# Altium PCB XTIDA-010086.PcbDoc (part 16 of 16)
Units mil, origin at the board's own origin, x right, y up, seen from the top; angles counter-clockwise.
Board outline 14763.78 x 8267.72 mil, 6 copper layers (Top Layer, GND Layer, Signal Layer 1, Signal Layer 2, Power Layer, Bottom Layer), stack 62 mil thick; 1933 components, 1002 nets, 4886 pads, 6482 vias.
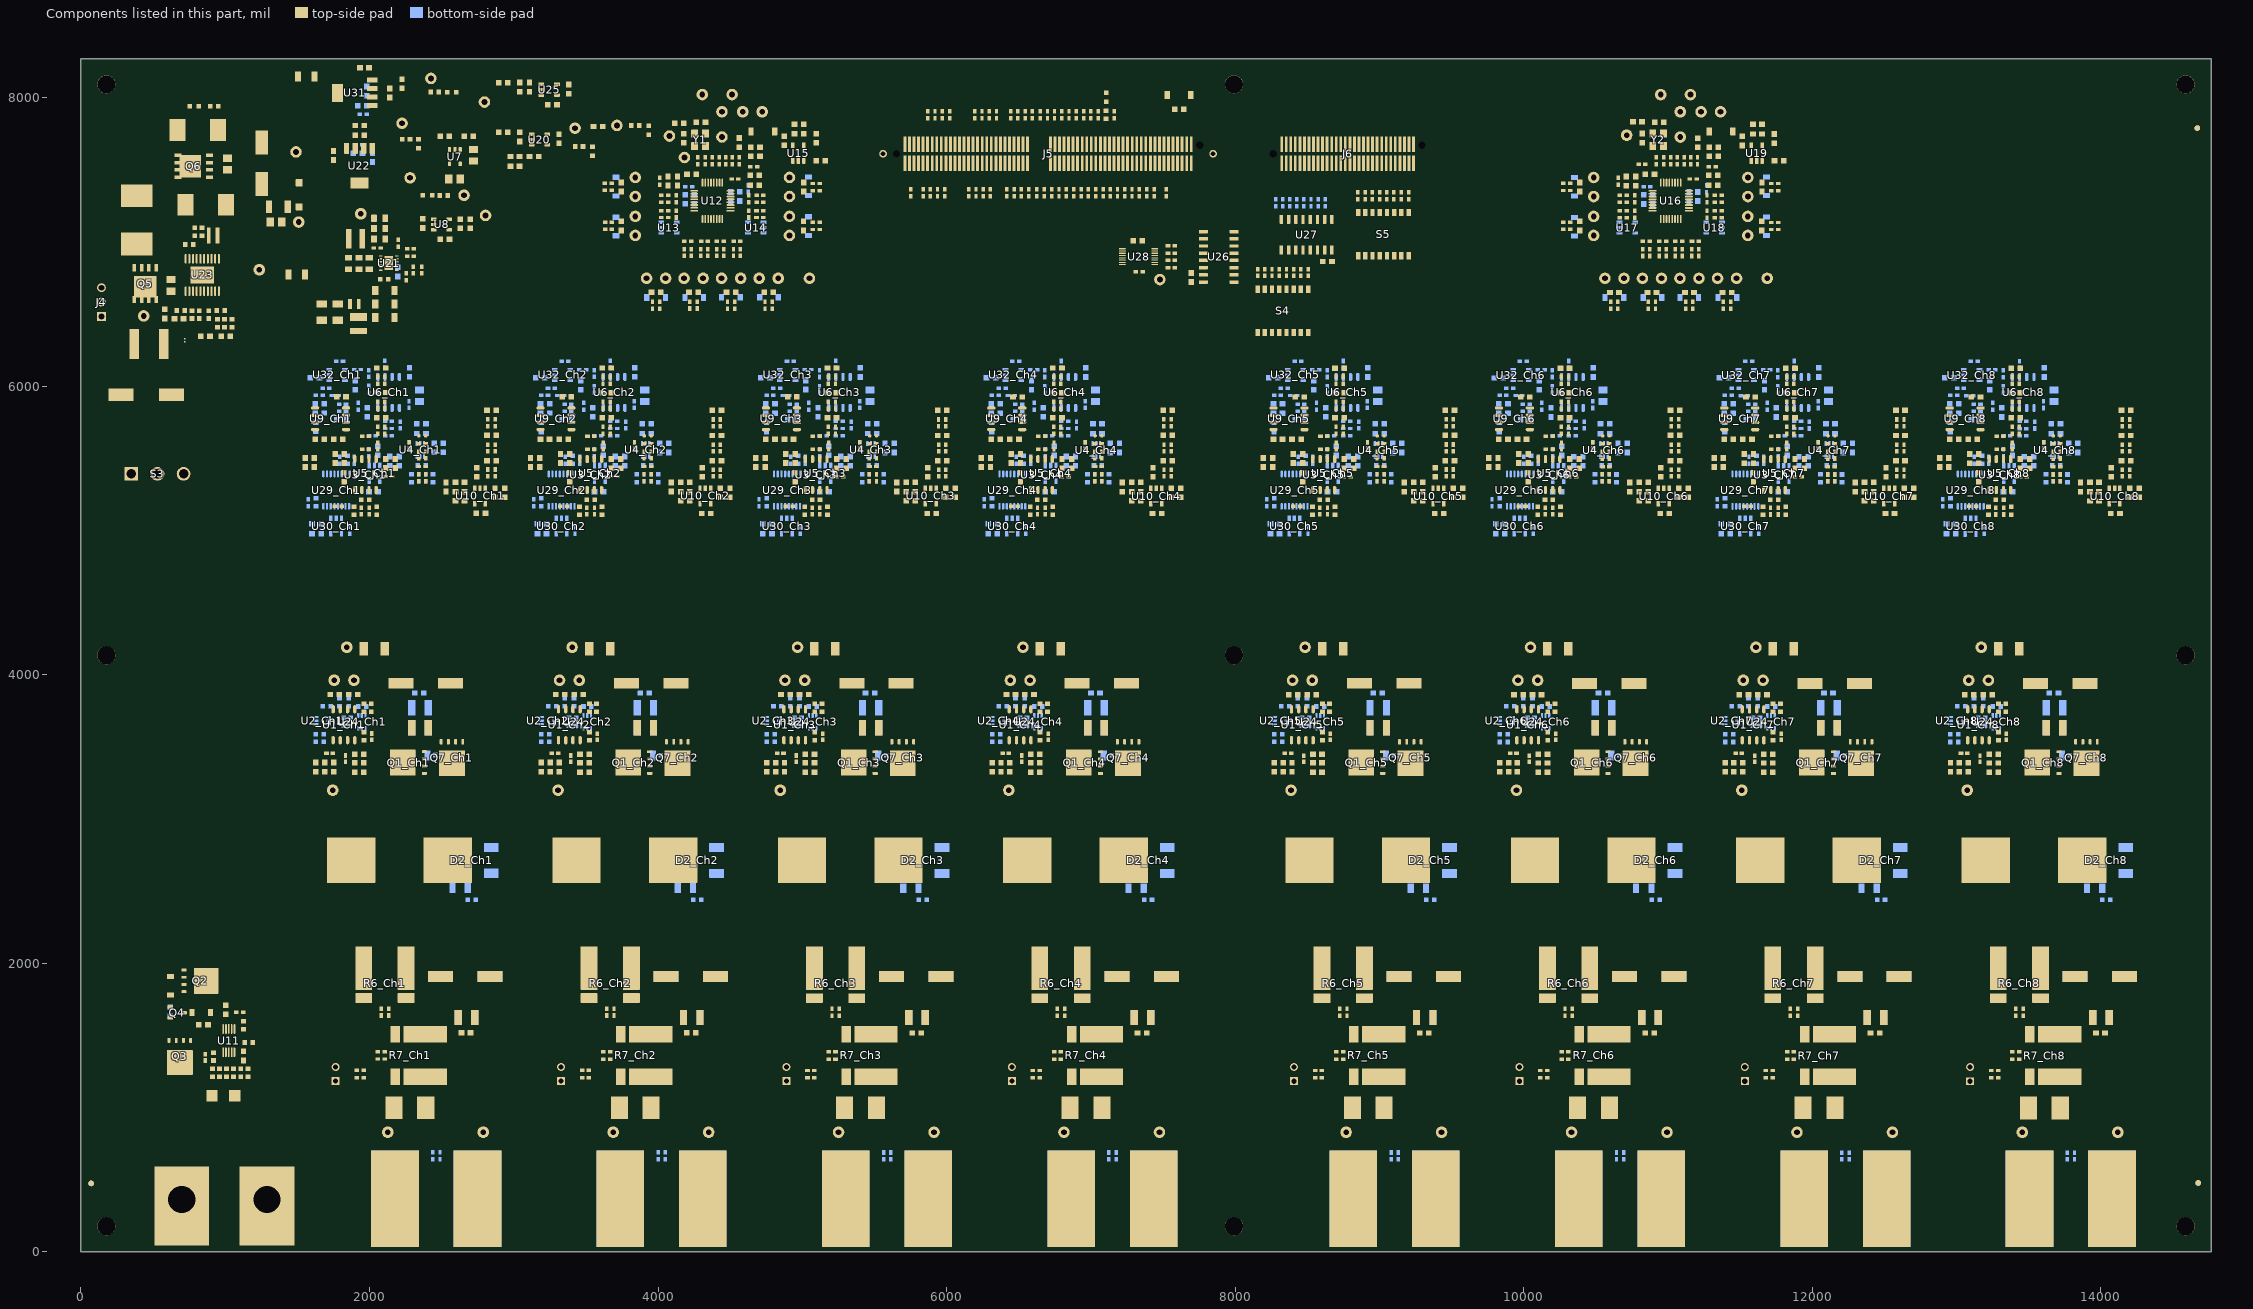
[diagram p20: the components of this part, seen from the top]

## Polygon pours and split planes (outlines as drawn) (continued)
SW_Ch3 on Bottom Layer "SW_CH3_L06_P431" (solid, remove dead copper, pour order 431): 21 vertices, not listed, extent 5483,2477.84 5840,3481.84
NetC3_Ch3_1 on Bottom Layer "NETC3_CH3_1_L06_P423" (solid, remove dead copper, pour order 423): 5194.43,3265.42 5206,3253.84 5434,3253.84 5443,3262.84 5443,4221.84 5433,4231.84 5202,4231.84 5194.43,4224.27
NetF1_Ch3_2 on Bottom Layer "NETF1_CH3_2_L06_P415" (solid, remove dead copper, pour order 415): 5360,1119.84 5369,1110.84 5434,1110.84 5445,1099.84 5445,862.84 5477,830.84 5745,830.84 5758,843.84 5758,1281.84 5748,1291.84 5375,1291.84 5360,1276.84
NetF1_Ch3_1 on Bottom Layer "NETF1_CH3_1_L06_P407" (solid, remove dead copper, pour order 407): 5355,1077.84 5358,1074.84 5358,886.84 5488,756.84 5488,51.84 5470,33.84 4811,33.84 4797,47.84 4797,1067.84 4807,1077.84
NetF1_Ch2_1 on Bottom Layer "NETF1_CH2_1_L06_P406" (solid, remove dead copper, pour order 406): 3793,1077.92 3796,1074.92 3796,886.92 3926,756.92 3926,51.92 3908,33.92 3249,33.92 3235,47.92 3235,1067.92 3245,1077.92
NetF1_Ch2_2 on Bottom Layer "NETF1_CH2_2_L06_P414" (solid, remove dead copper, pour order 414): 3798,1119.92 3807,1110.92 3872,1110.92 3883,1099.92 3883,862.92 3915,830.92 4183,830.92 4196,843.92 4196,1281.92 4186,1291.92 3813,1291.92 3798,1276.92
NetC3_Ch2_1 on Bottom Layer "NETC3_CH2_1_L06_P422" (solid, remove dead copper, pour order 422): 3632.43,3265.5 3644,3253.92 3872,3253.92 3881,3262.92 3881,4221.92 3871,4231.92 3640,4231.92 3632.43,4224.35
SW_Ch2 on Bottom Layer "SW_CH2_L06_P430" (solid, remove dead copper, pour order 430): 21 vertices, not listed, extent 3921,2477.92 4278,3481.92
NetL2_Ch2_2 on Bottom Layer "NETL2_CH2_2_L06_P438" (solid, remove dead copper, pour order 438): 3249.13,2889.92 3235,2875.79 3235,1823.92 3246,1812.92 3581,1812.92 3589,1820.92 3589,2111.92 3624,2146.92 3624,2882.92 3617,2889.92
NetC9_Ch2_1 on Bottom Layer "NETC9_CH2_1_L06_P446" (solid, remove dead copper, pour order 446): 17 vertices, not listed, extent 3748,1442.92 4219,2213.92
PGND on Bottom Layer "PGND_L06_P454" (solid, remove dead copper, pour order 454): 25 vertices, not listed, extent 3940.5,33.92 4625,4231.92
PGND on Bottom Layer "PGND_L06_P453" (solid, remove dead copper, pour order 453): 25 vertices, not listed, extent 2378.5,34 3063,4232
NetC9_Ch1_1 on Bottom Layer "NETC9_CH1_1_L06_P445" (solid, remove dead copper, pour order 445): 17 vertices, not listed, extent 2186,1443 2657,2214
NetL2_Ch1_2 on Bottom Layer "NETL2_CH1_2_L06_P437" (solid, remove dead copper, pour order 437): 1687.13,2890 1673,2875.87 1673,1824 1684,1813 2019,1813 2027,1821 2027,2112 2062,2147 2062,2883 2055,2890
SW_Ch1 on Bottom Layer "SW_CH1_L06_P429" (solid, remove dead copper, pour order 429): 21 vertices, not listed, extent 2359,2478 2716,3482
NetC3_Ch1_1 on Bottom Layer "NETC3_CH1_1_L06_P421" (solid, remove dead copper, pour order 421): 2070.43,3265.57 2082,3254 2310,3254 2319,3263 2319,4222 2309,4232 2078,4232 2070.43,4224.43
NetF1_Ch1_2 on Bottom Layer "NETF1_CH1_2_L06_P413" (solid, remove dead copper, pour order 413): 2236,1120 2245,1111 2310,1111 2321,1100 2321,863 2353,831 2621,831 2634,844 2634,1282 2624,1292 2251,1292 2236,1277
NetF1_Ch1_1 on Bottom Layer "NETF1_CH1_1_L06_P405" (solid, remove dead copper, pour order 405): 2231,1078 2234,1075 2234,887 2364,757 2364,52 2346,34 1687,34 1673,48 1673,1068 1683,1078
10V_Gate on Bottom Layer "10V_GATE_L06_P388" (solid, remove dead copper, pour order 388): 1548,7671 1529,7690 1150.85,7690 972,7507.7 972,6609.7 986,6595.7 1096,6595.7 1104,6603.7 1104,7401.7 1246.65,7544.35 1516.35,7544.35 1548,7576
no net on Bottom Layer "NONET_L06_P387" (solid, remove dead copper, pour order 387): 961.17,6613.05
NetD7_1 on Bottom Layer "NETD7_1_L06_P368" (solid, remove dead copper, pour order 368): 879,1355 879,1356.86 896,1373.86 896,1443 888,1451 815,1451 808,1444 808,1367 820,1355
PGND on GND Layer "PGND_L02_P564" (solid, remove dead copper, pour order 564): 86 vertices, not listed, extent 38,33.45 14667,8230
DGND on GND Layer "DGND_L02_P570" (solid, remove dead copper, pour order 570): 44 vertices, not listed, extent 1577,6299.47 11467,8230
AGND on GND Layer "AGND_L02_P566" (solid, remove dead copper, pour order 566): 51 vertices, not listed, extent 1505,4884 14667,8230
12VP on GND Layer "12VP_L02_P562" (solid, remove dead copper, pour order 562): 24 vertices, not listed, extent 377,38 957,1399
12V_Out on GND Layer "12V_OUT_L02_P550" (solid, remove dead copper, pour order 550): 82 vertices, not listed, extent 535,1686 13318.12,4859
PGND on GND Layer "PGND_L02_P548" (solid, remove dead copper, pour order 548): 1534,38
PGND on GND Layer "PGND_L02_P532" (solid, remove dead copper, pour order 532): 31 vertices, not listed, extent 854,38 1556,3407
PGND on Power Layer "PGND_L05_P604" (solid, remove dead copper, pour order 604): 86 vertices, not listed, extent 38,33.45 14667,8230
DVDD on Power Layer "DVDD_L05_P588" (solid, remove dead copper, pour order 588): 38 vertices, not listed, extent 1577,6299.47 11467,8230
5V on Power Layer "5V_L05_P586" (solid, remove dead copper, pour order 586): 46 vertices, not listed, extent 1505,4884 14667,8230
12VP on Power Layer "12VP_L05_P558" (solid, remove dead copper, pour order 558): 24 vertices, not listed, extent 377,38 957,1399
12V_Out on Power Layer "12V_OUT_L05_P552" (solid, remove dead copper, pour order 552): 82 vertices, not listed, extent 535,1686 13318.12,4859
PGND on Power Layer "PGND_L05_P538" (solid, remove dead copper, pour order 538): 31 vertices, not listed, extent 854,38 1556,3407
12V_Out on Top Solder "12V_OUT_L01_P518" (solid, pour order 362): 82 vertices, not listed, extent 535,1686 13318.12,4859
12V_Out on Bottom Solder "12V_OUT_L01_P518" (solid): 82 vertices, not listed, extent 535,1686 13318.12,4859
PGND on Signal Layer 1 "PGND_L03_P590" (solid, remove dead copper, pour order 590): 86 vertices, not listed, extent 38,33.45 14667,8230
PGND on Signal Layer 2 "PGND_L04_P592" (solid, remove dead copper, pour order 592): 86 vertices, not listed, extent 38,33.45 14667,8230

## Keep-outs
Keep-Out Layer:
  the board outline again, w10
  text ".Layer_Name" at -397.26,-1209.34 h60

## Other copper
Top Layer:
  pour cut-out: 740.67,6829.08 923.4,6829.08 924,6828.48 967.5,6828.48 968,6827.99 968,6840 740.67,6840
  pour cut-out: 727.86,6711.7 955.15,6711.7 955.15,6698.85 954,6697.7 729.16,6697.7 727.86,6699
  pour cut-out: 587.49,6820.21 587.49,6711 566,6711 563,6714 563,6795.72
  pour cut-out: 4294.1,7254.48 4294.1,7212.51 4300.3,7206.31 4452.74,7206.31 4457.3,7210.88 4457.3,7253.6 4458.02,7254.31 4458.74,7253.59 4466.19,7253.59 4466.19,7201.69 4458.3,7193.8 4294.87,7193.8 4286.9,7201.77 4286.9,7254.31
  pour cut-out: 10935.8,7254.17 10935.8,7212.2 10942,7206 11094.44,7206 11099,7210.56 11099,7253.28 11099.72,7254 11100.45,7253.27 11107.89,7253.27 11107.89,7201.38 11100,7193.48 10936.58,7193.48 10928.6,7201.46 10928.6,7254
  pour cut-out: 9356.97,7747.43 9356.97,7471 5366.54,7471 5366.54,7747.43
  pour cut-out: 10807.7,7442 10807.7,7394.36 10816.06,7386 10866.54,7386 10866.54,7442.63
  text ".Layer_Name" at -397.26,-1209.34 h60
GND Layer:
  text "'.Layer_Name'" at -124,-1208.85 h60
Power Layer:
  text "'.Layer_Name'" at -165,-1213.85 h60
Signal Layer 1:
  text "'.Layer_Name'" at -178,-1217.85 h60
Signal Layer 2:
  text "'.Layer_Name'" at -181,-1217.85 h60
Bottom Layer:
  text ".Layer_Name" at -397.26,-1209.34 h60

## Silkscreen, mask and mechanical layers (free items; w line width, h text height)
Top Overlay:
  drawing of 428 lines, arcs and shapes, not listed
  text "5V_D" at 2500.24,8153 h40
  text "DIN1" at 4273,8117.98 h40
  text "DRDY1" at 4459,8118 h40
  text "DIN2" at 10914.7,8117.67 h40
  text "DRDY2" at 11100.7,8117.69 h40
  text ".PRJ_Number" at 12831,8005 h150
  text "-E2" at 13744,8005 h150
  text "RESET1" at 4677,7999 h40
  text "RESET1" at 11318.7,7998.69 h40
  text "SCLK1" at 4449,7971 h40 r90
  text "SCLK2" at 11090.7,7970.69 h40 r90
  text "CS1" at 4651,7960 h40 r90
  text "CS2" at 11292.7,7959.69 h40 r90
  text "A" at 3898.47,7928.33 h30
  text "DVDD" at 3665,7910 h40
  text "AVDD" at 3381,7893 h40
  text "DGND" at 2755,7874.47 h40
  text "5V" at 2112,7793 h40
  text "DGND" at 4060,7791 h40 r90
  text "DOUT2" at 11047,7789 h40
  text "DOUT1" at 4405,7787 h40
  text "180" at 9233,7786 h30
  text "120" at 7694,7785.15 h30
  text "122" at 8256,7783 h30
  text "2" at 5699,7782 h30
  text "10V_Gate" at 1422,7733 h40
  text "B" at 10421,7677.7 h30
  text "DGND" at 10665,7649.53 h40
  text "C2000_CLK" at 3932,7610 h40
  text "IoutP1 /" at 3606,7483 h40
  text "IoutP5 /" at 10247.7,7482.69 h40
  text "/ VoutP4" at 5043,7468 h40
  text "/ VoutP8" at 11684.7,7467.69 h40
  text "B" at 11063,7459.7 h30
  text "A" at 4416,7458.33 h30
  text "1" at 5706,7409 h30
  text "121" at 8269,7408 h30
  text "179" at 9232,7407 h30
  text "119" at 7692,7403.15 h30
  text "AGND" at 2217,7352 h40
  text "2.5V" at 2728,7283 h40
  text "IoutN1 /" at 3583,7267 h40
  text "IoutN5 /" at 10224.7,7266.69 h40
  text "/ VoutN4" at 5050,7251.7 h40
  text "/ VoutN8" at 11691.7,7251.39 h40
  text "VoutN1 /" at 3558,7214 h40
  text "VoutN5 /" at 10199.7,7213.69 h40
  text "-5V" at 1810.13,7200.47 h40
  text "/ IoutN4" at 5043,7199 h40
  text "/ IoutN8" at 11684.7,7198.69 h40
  text "-2.5V" at 2878,7143 h40
  text "10V" at 1482,7040 h40
  text "VoutP1 /" at 3564,6996 h40
  text "VoutP5 /" at 10205.7,6995.69 h40
  text "/ IoutP4" at 5037,6981 h40
  text "/ IoutP8" at 11678.7,6980.69 h40
  text "CHANNEL 1" at 3599.35,6923 h50
  text "CHANNEL 5" at 10241.05,6922.69 h50
  text "CHANNEL 4" at 4889.35,6920 h50
  text "CHANNEL 8" at 11531.05,6919.69 h50
  text "PGND" at 1193,6712 h40
  text "AGND" at 5008,6653 h40
  text "AGND" at 11637,6653 h40
  text "DGND" at 7437,6616 h40
  text "IoutP2 /" at 3876,6510 h40 r90
  text "IoutP6 /" at 10517.7,6509.69 h40 r90
  text "IoutP3 /" at 4417,6495 h40 r90
  text "IoutP7 /" at 11058.7,6494.69 h40 r90
  text "IoutN2 /" at 4099.38,6487.17 h40 r90
  text "IoutN3 /" at 4634,6487 h40 r90
  text "IoutN6 /" at 10741.08,6486.86 h40 r90
  text "IoutN7 /" at 11274,6487 h40 r90
  text "12V_IN" at 256,6486.33 h40
  text "VoutP3 /" at 4882,6477 h40 r90
  text "VoutP7 /" at 11523.7,6476.69 h40 r90
  text "VoutP2 /" at 4358,6468 h40 r90
  text "VoutP6 /" at 10999.7,6467.69 h40 r90
  text "VoutN2 /" at 4139,6462 h40 r90
  text "VoutN6 /" at 10780.7,6461.69 h40 r90
  text "VoutN3 /" at 4670,6459 h40 r90
  text "VoutN7 /" at 11311.7,6458.69 h40 r90
  text "CHANNEL 2" at 3988.35,6414 h50
  text "CHANNEL 3" at 4508.35,6414 h50
  text "CHANNEL 6" at 10630.05,6414 h50
  text "CHANNEL 7" at 11150.05,6414 h50
  text "CHANNEL 1" at 2495,6072 h100
  text "CHANNEL 2" at 4057,6071.92 h100
  text "CHANNEL 3" at 5619,6071.84 h100
  text "CHANNEL 4" at 7181,6071.76 h100
  text "CHANNEL 5" at 9136.7,6071.69 h100
  text "CHANNEL 6" at 10693.7,6071.61 h100
  text "CHANNEL 7" at 12260.7,6071.53 h100
  text "CHANNEL 8" at 13822.7,6071.45 h100
  text "12V_Out" at 1709,4046 h40
  text "12V_Out" at 3271,4045.92 h40
  text "12V_Out" at 4833,4045.84 h40
  text "12V_Out" at 6395,4045.76 h40
  text "12V_Out" at 8350.7,4045.69 h40
  text "12V_Out" at 9912.7,4045.61 h40
  text "12V_Out" at 11474.7,4045.53 h40
  text "12V_Out" at 13036.7,4045.45 h40
  text "LI" at 1666,3979 h40
  text "HI" at 1960,3979 h40
  text "LI" at 3228,3978.92 h40
  text "HI" at 3522,3978.92 h40
  text "LI" at 4790,3978.84 h40
  text "HI" at 5084,3978.84 h40
  text "LI" at 6352,3978.76 h40
  text "HI" at 6646,3978.76 h40
  text "LI" at 8307.7,3978.69 h40
  text "HI" at 8601.7,3978.69 h40
  text "LI" at 9869.7,3978.61 h40
  text "HI" at 10163.7,3978.61 h40
  text "LI" at 11431.7,3978.53 h40
  text "HI" at 11725.7,3978.53 h40
  text "LI" at 12993.7,3978.45 h40
  text "HI" at 13287.7,3978.45 h40
  text "SW" at 1627,3156 h40
  text "SW" at 3189,3155.92 h40
  text "SW" at 6313,3155.76 h40
  text "SW" at 8268.7,3155.69 h40
  text "SW" at 4728.63,3155.55 h40
  text "SW" at 9830.7,3155.61 h40
  text "SW" at 11392.7,3155.53 h40
  text "SW" at 12954.7,3155.45 h40
  text "-VSense" at 1680,1246 h40 r90
  text "-VSense" at 3242,1245.92 h40 r90
  text "-VSense" at 4804,1245.84 h40 r90
  text "-VSense" at 6366,1245.76 h40 r90
  text "-VSense" at 8321.7,1245.69 h40 r90
  text "-VSense" at 9883.7,1245.61 h40 r90
  text "-VSense" at 11445.7,1245.53 h40 r90
  text "-VSense" at 13007.7,1245.45 h40 r90
  text "+VSense" at 1680,1081 h40 r90
  text "+VSense" at 3242,1080.92 h40 r90
  text "+VSense" at 4804,1080.84 h40 r90
  text "+VSense" at 6366,1080.76 h40 r90
  text "+VSense" at 8321.7,1080.69 h40 r90
  text "+VSense" at 9883.7,1080.61 h40 r90
  text "+VSense" at 11445.7,1080.53 h40 r90
  text "+VSense" at 13007.7,1080.45 h40 r90
  text "PGND" at 2669,895 h100
  text "PGND" at 4231,894.92 h100
  text "PGND" at 5793,894.84 h100
  text "PGND" at 7355,894.76 h100
  text "PGND" at 9310.7,894.69 h100
  text "PGND" at 10872.7,894.61 h100
  text "PGND" at 12434.7,894.53 h100
  text "PGND" at 13996.7,894.45 h100
  text "B+" at 1974,730 h100
  text "B-" at 2885,730 h100
  text "B+" at 3536,729.92 h100
  text "B-" at 4447,729.92 h100
  text "B+" at 5098,729.84 h100
  text "B-" at 6009,729.84 h100
  text "B+" at 6660,729.76 h100
  text "B-" at 7571,729.76 h100
  text "B+" at 8615.7,729.69 h100
  text "B-" at 9526.7,729.69 h100
  text "B+" at 10177.7,729.61 h100
  text "B-" at 11088.7,729.61 h100
  text "B+" at 11739.7,729.53 h100
  text "B-" at 12650.7,729.53 h100
  text "B+" at 13301.7,729.45 h100
  text "B-" at 14212.7,729.45 h100
  text "PGND" at 1161,675 h100
  text "INPUT" at 570,674 h100
  text ".Layer_Name" at -397.26,-1209.34 h60
Bottom Overlay:
  drawing of 280 lines, arcs and shapes, not listed
  text "CHANNEL 1" at 2983,6051 h100
  text "CHANNEL 2" at 4545,6050.92 h100
  text "CHANNEL 3" at 6107,6050.84 h100
  text "CHANNEL 4" at 7669,6050.76 h100
  text "CHANNEL 5" at 9624.7,6050.69 h100
  text "CHANNEL 6" at 11186.7,6050.61 h100
  text "CHANNEL 7" at 12748.7,6050.53 h100
  text "CHANNEL 8" at 14310.7,6050.45 h100
  text ".Layer_Name" at -397.26,-1209.34 h60
Top Paste:
  text ".Layer_Name" at -397.26,-1209.34 h60
Bottom Paste:
  text ".Layer_Name" at -397.26,-1209.34 h60
Top Solder:
  text ".Layer_Name" at -397.26,-1209.34 h60
  text ".Layer_Name" at -397.26,-1209.34 h60
Bottom Solder:
  text ".Layer_Name" at -397.26,-1209.34 h60
Drill Guide:
  text ".Layer_Name" at -397.26,-1209.34 h60
M1 Board Outline:
  the board outline again, w10
M2 Board Dimensions:
  rectangle: -974.26,-625.85 -849.26,-500.85
  rectangle: -849.26,-750.85 -474.26,-625.85
  lines w7: -974.26,-625.85 25.74,-625.85 ; -849.26,-750.85 -849.26,-500.85 ; -724.26,-750.85 -724.26,-500.85 ; -474.26,-750.85 -474.26,-500.85 ; -224.26,-750.85 -224.26,-500.85 ; -974.26,-750.85 25.74,-750.85 25.74,-500.85 -974.26,-500.85 -974.26,-750.85
M3 3D STEP Top:
  text ".Layer_Name" at -397.26,-1209.34 h60
M4 3D STEP Bottom:
  text ".Layer_Name" at -397.26,-1209.34 h60
M5 Assembly Top:
  drawing of 180 lines, arcs and shapes, not listed
  text "2" at 5696,7668 h18
  text "122" at 8229,7667 h18
  text "120" at 7691,7663 h18
  text "180" at 9230,7663 h18
  text "121" at 8230,7519 h18
  text "179" at 9231,7517 h18
  text "119" at 7693,7516 h18
  text "1" at 5702,7513 h18
  text "CHANNEL 1" at 3597.35,6925 h50
  text "CHANNEL 5" at 10239.05,6924.69 h50
  text "CHANNEL 4" at 4887.35,6922 h50
  text "CHANNEL 8" at 11529.05,6921.69 h50
  text "CHANNEL 2" at 3986.35,6414 h50
  text "CHANNEL 3" at 4506.35,6414 h50
  text "CHANNEL 6" at 10628.05,6414 h50
  text "CHANNEL 7" at 11148.05,6414 h50
  text "CHANNEL 1" at 2490,6072 h100
  text "CHANNEL 2" at 4052,6071.92 h100
  text "CHANNEL 3" at 5614,6071.84 h100
  text "CHANNEL 4" at 7176,6071.76 h100
  text "CHANNEL 5" at 9131.7,6071.69 h100
  text "CHANNEL 6" at 10693.7,6071.61 h100
  text "CHANNEL 7" at 12255.7,6071.53 h100
  text "CHANNEL 8" at 13817.7,6071.45 h100
  text "COMPONENTS MARKED 'DNP' SHOULD NOT BE POPULATED." at 179.24,-669.35 h18
  text "ASSEMBLY VARIANT:" at 178.74,-784.85 h18
  text ".VariantName" at 1214.74,-784.85 h18
  text "PCB VIEWED FROM TOP SIDE" at -1202.76,-1006.52 h18
  text "BOARD #:" at 1273.74,-1006.52 h18
  text "REV:" at 2663.74,-1006.52 h18
  text ".PCB_Rev" at 2955.24,-1006.52 h18
  text "SVN REV:" at 3501.74,-1006.52 h18
  text ".VersionControl_RevNumber" at 4007.74,-1006.52 h18
  text ".PRJ_Number" at 1716,-1010.85 h18
  text ".TID" at 1651,-1206 h18
  text "TID #:" at 1273.74,-1209.85 h18
  text "LAYER NAME =" at -1200.76,-1214.34 h18
  text ".layer_Name" at -323.26,-1224.85 h18
  text ".plot_File_Name" at -528.26,-1404.85 h18
  text "PLOT NAME =" at -1202.76,-1415.19 h18
  text "GENERATED    :" at 1275.74,-1415.19 h18
  text ".Print_Date" at 2145.24,-1415.19 h18
  text ".Print_Time" at 2874.24,-1415.19 h18
  text "TEXAS INSTRUMENTS" at 4138.74,-1415.19 h18
M6 Assembly Bottom:
  circle w10: c1702.21,6042 r7.74
  circle w10: c1731.35,5102 r7.74
  circle w10: c3265.21,6039 r7.74
  circle w10: c3292.21,5106 r7.74
  circle w10: c4825.21,6040.53 r7.74
  circle w10: c4855.21,5105 r7.74
  circle w10: c6390.21,6042 r7.74
  circle w10: c6415.81,5104 r7.74
  circle w10: c8345.21,6041 r7.74
  circle w10: c8373.3,5104 r7.74
  circle w10: c9909.21,6038 r7.74
  circle w10: c9935.21,5103 r7.74
  circle w10: c11468.21,6039 r7.74
  circle w10: c11496.66,5104 r7.74
  circle w10: c13032.21,6041 r7.74
  circle w10: c13059.3,5102 r7.74
  circle w10: c1997,5468 r8.94
  circle w10: c2752,2806 r8.94
  circle w10: c3560,5468 r8.94
  circle w10: c4312,2806 r8.94
  circle w10: c5122.6,5468.56 r8.94
  circle w10: c5871,2807 r8.94
  circle w10: c6684,5468 r8.94
  circle w10: c7436,2803 r8.94
  circle w10: c8639,5467 r8.94
  circle w10: c9393,2805 r8.94
  circle w10: c10202,5468 r8.94
  circle w10: c10956,2804 r8.94
  circle w10: c11763,5468 r8.94
  circle w10: c12514,2803 r8.94
  circle w10: c13324,5469 r8.94
  circle w10: c14077,2806 r8.94
  circle w10: c10644,7061.9 r8.28
  circle w10: c11392,7134.69 r8.28
  circle w10: c4002,7062.9 r8.28
  circle w10: c4751,7135 r8.28
  lines w6: 1938,36 1580,36 1580,4850 1517,4913 1517,6215 3063,6215 3063,4225 3063,36 2936,36 ; 2376,36 2547,36 ; 3500,35.92 3142,35.92 3142,4849.92 3079,4912.92 3079,6214.92 4625,6214.92 4625,4224.92 4625,35.92 4498,35.92 ; 3938,35.92 4109,35.92 ; 5062,35.84 4704,35.84 4704,4849.84 4641,4912.84 4641,6214.84 6187,6214.84 6187,4224.84 6187,35.84 6060,35.84 ; 5500,35.84 5671,35.84 ; 6624,35.76 6266,35.76 6266,4849.76 6203,4912.76 6203,6214.76 7749,6214.76 7749,4224.76 7749,35.76 7622,35.76 ; 7062,35.76 7233,35.76 ; 8579.7,35.69 8221.7,35.69 8221.7,4849.69 8158.7,4912.69 8158.7,6214.69 9704.7,6214.69 9704.7,4224.69 9704.7,35.69 9577.7,35.69 ; 9017.7,35.69 9188.7,35.69 ; 10141.7,35.61 9783.7,35.61 9783.7,4849.61 9720.7,4912.61 9720.7,6214.61 11266.7,6214.61 11266.7,4224.61 11266.7,35.61 11139.7,35.61 ; 10579.7,35.61 10750.7,35.61 ; 11703.7,35.53 11345.7,35.53 11345.7,4849.53 11282.7,4912.53 11282.7,6214.53 12828.7,6214.53 12828.7,4224.53 12828.7,35.53 12701.7,35.53 ; 12141.7,35.53 12312.7,35.53 ; 13265.7,35.45 12907.7,35.45 12907.7,4849.45 12844.7,4912.45 12844.7,6214.45 14390.7,6214.45 14390.7,4224.45 14390.7,35.45 14263.7,35.45 ; 13703.7,35.45 13874.7,35.45
  lines w10: -1266.76,-1078.18 5335.24,-1078.18 ; -1264.76,-1281.52 5335.24,-1281.52 ; 141.24,-1491.35 141.24,-1288.52 ; 763.24,-1078.18 763.24,-874.85 ; 1603.24,-1078.18 1603.24,-874.85 ; 2870.24,-1484.85 2870.24,-874.85 ; 3759.24,-1484.85 5334.74,-1484.85 5334.74,-874.85 -1266.76,-874.85 -1266.76,-1484.85 1330.24,-1484.85 5335.24,-1484.85 5335.24,-874.85
  text "CHANNEL 1" at 2980,6054 h100
  text "CHANNEL 2" at 4542,6053.92 h100
  text "CHANNEL 3" at 6104,6053.84 h100
  text "CHANNEL 4" at 7666,6053.76 h100
  text "CHANNEL 5" at 9621.7,6053.69 h100
  text "CHANNEL 6" at 11183.7,6053.61 h100
  text "CHANNEL 7" at 12745.7,6053.53 h100
  text "CHANNEL 8" at 14307.7,6053.45 h100
  text "C150" at 3232,4972 h18
  text "C150" at 8307,4970 h18
  text "C150" at 6353,4968 h18
  text "C150" at 11431,4967 h18
  text "C150" at 11431,4967 h18
  text "C150" at 12990,4967 h18
  text "C150" at 9874,4966 h18
  text "C150" at 4791,4965 h18
  text "COMPONENTS MARKED 'DNP' SHOULD NOT BE POPULATED." at 5127.74,-668.85 h18
  text ".VariantName" at 4083.74,-784.85 h18
  text "ASSEMBLY VARIANT:" at 5122.74,-784.85 h18
  text "REV:" at 1231,-1001.85 h18
  text ".PCB_Rev" at 864,-1003.85 h18
  text ".VersionControl_RevNumber" at 61.24,-1007.02 h18
  text "SVN REV:" at 567.24,-1007.02 h18
  text "BOARD #:" at 2795.24,-1007.02 h18
  text "PCB VIEWED FROM BOTTOM SIDE" at 5271.74,-1007.02 h18
  text ".PRJ_Number" at 2346,-1007.85 h18
  text "LAYER NAME =" at 5039,-1192 h18
  text ".layer_Name" at 4788.74,-1193.85 h18
  text ".TID" at 2619,-1210 h18
  text "TID #:" at 2795.24,-1210.35 h18
  text "TEXAS INSTRUMENTS" at -69.76,-1415.69 h18
  text ".Print_Time" at 1194.74,-1415.69 h18
  text ".Print_Date" at 1923.74,-1415.69 h18
  text "GENERATED    :" at 2793.24,-1415.69 h18
  text ".plot_File_Name" at 4466.24,-1415.69 h18
  text "PLOT NAME =" at 5271.74,-1415.69 h18
M9 Title Sheet:
  drawing of 71 lines, arcs and shapes, not listed
  text "1" at -422.42,11436.87 h70
  text "2" at 2277.55,11435.5 h70
  text "3" at 4766.89,11435.5 h70
  text "4" at 7273.56,11435.5 h70
  text "5" at 9772.55,11435.5 h70
  text "6" at 22447.24,11435.65 h70
  text "A" at -1390.76,6542.65 h70
  text "A" at 23595.24,6542.65 h70
  text "B" at -1390.76,4162.65 h70
  text "B" at 23595.24,4162.65 h70
  text "C" at -1390.76,1787.65 h70
  text "C" at 23595.24,1787.65 h70
  text "PROJECT TITLE:" at 20596.5,-40.88 h45
  text ".PRJ_Title" at 20605.24,-206.68 h70
  text "DESIGNED FOR:" at 20555.24,-374.35 h45
  text "PUBLIC RELEASE" at 20605.24,-514.35 h70
  text "D" at -1390.76,-582.35 h70
  text "D" at 23595.24,-582.35 h70
  text "FILE NAME:" at 20555.24,-674.35 h45
  text ".PCB_File_Name_No_Path" at 20605.24,-794.35 h70
  text "Texas Instruments (TI) and/or its licensors do not warrant the accuracy or completeness of this specification" at 5399.74,-956.19 h45
  text "ENGINEER:" at 20555.24,-964.35 h45
  text "LAYOUT BY:" at 22060.24,-964.35 h45
  text "or any information contained therein. TI and/or its licensors do not warrant that this design will meet" at 5354.75,-1068.85 h45
  text "Shaury Anand" at 20605.24,-1119.34 h50
  text "Avinash N" at 22110.74,-1119.34 h70
  text "the specifications, will be suitable for your application or fit for any particular purpose, or will operate in" at 5354.75,-1181.52 h45
  text "ALTIUM DESIGNER VERSION:" at 22060.24,-1274.35 h45
  text "an implementation. TI and/or its licensors do not warrant that the design is production worthy. You should" at 5354.75,-1294.18 h45
  text "completely validate and test your design implementation to confirm the system functionality for your application." at 5399.74,-1406.85 h45
  text ".print_Scale" at 20605.24,-1407.68 h70
  text ".Application_BuildNumber" at 22110.74,-1407.68 h70
  text "1" at -234.42,-1614.35 h70
  text "2" at 2261.24,-1614.35 h70
  text "3" at 4750.58,-1614.35 h70
  text "4" at 7257.25,-1614.35 h70
  text "5" at 15522.24,-1614.35 h70
  text "6" at 22447.24,-1614.35 h70
M10 Fab Notes:
  drawing of 189 lines, arcs and shapes, not listed
  text "ALL VIAS ARE  TENTED EXCEPT THERMAL VIAS" at 20521.74,6296.15 h60
  text "THIS IS NOT AN IMPEDENCE CONTROLLED  BOARD" at 20513.74,6173.15 h60
  text "DESIGN INFORMATION" at 21593.76,6005.32 h60
  text "MIN. TRACK WIDTH:" at 20949.2,5873.2 h60
  text "6" at 22045.44,5873.2 h60
  text "MIL" at 22200.2,5873.2 h60
  text "6" at 22050,5764 h60
  text "MIN. CLEARANCE:" at 20949.2,5749.07 h60
  text "MIL" at 22200.2,5749.07 h60
  text "MIN. VIA PAD SIZE:" at 20949.2,5624.95 h60
  text "12" at 22015.45,5624.95 h60
  text "MIL" at 22200.2,5624.95 h60
  text "5.90 MIL" at 21644.2,5495.05 h60
  text "MINIMUM ANNULAR RING" at 20619.97,5486.82 h60
  text "EXTERNAL" at 22352.2,5486.82 h60
  text "PER" at 20819.97,5376.7 h60
  text "IPC-D-275 CLASS 2 LEVEL C" at 21039.97,5376.69 h60
  text "MIL, HOLES" at 22528.2,5276.22 h60
  text "+/-" at 22135.74,5267.63 h60
  text "+/-" at 22989.74,5267.63 h60
  text "REGISTRATION TOLERANCES:" at 20619.97,5266.57 h60
  text "METAL" at 21819.74,5266.57 h60
  text "5" at 22395.94,5266.57 h60
  text "3" at 23228.94,5266.57 h60
  text "MIL" at 23345.2,5266.57 h60
  text "HOLE SIZE TOLERANCE (UNLESS OTHERWISE SPECIFIED):" at 20619.97,5168.25 h60
  text "+/-" at 22989.74,5165.38 h60
  text "3" at 23228.94,5164.32 h60
  text "MIL" at 23345.2,5164.32 h60
  text "MATERIAL:" at 20545.2,5026.67 h60
  text "FR-4 High Tg" at 21531.64,4898.15 h60
  text "X" at 21387.2,4890.16 h60
  text "FR-408" at 20966.2,4885.64 h60
  text "OTHER" at 22454.2,4885.64 h60
  text "63 MIL (1.6mm) +/-10%" at 21286.3,4742.61 h60
  text "X" at 21166.2,4740.16 h60
  text "THICKNESS:" at 20619.97,4734.39 h60
  text "OTHER" at 22571.2,4734.39 h60
  text "TOLERANCE:" at 20619.97,4596.07 h60
  text "X" at 21468.2,4596.07 h60
  text "ANSI IPC-6012 TYPE 3 CLASS 2" at 21646.22,4596.07 h60
  text "OTHER +/-" at 21646.2,4451.88 h60
  text "BOW & TWIST:" at 20619.97,4306.69 h60
  text "X" at 21468.2,4306.69 h60
  text "ANSI IPC-6012 TYPE 3 CLASS 2" at 21646.22,4306.69 h60
  text "OTHER +/-" at 21646.2,4160 h60
  text "DRILLING:" at 20545.2,4029.38 h60
  text "NC_DRILL FILES" at 22306.2,3924.19 h60
  text "REFERENCE:" at 20619.97,3920.25 h60
  text "X" at 21277.2,3920.16 h60
  text "AS SHOWN" at 21455.2,3920.25 h60
  text "X" at 22178.2,3920.25 h60
  text "OTHER" at 22604.2,3778 h60
  text "PTH COPPER THICKNESS:" at 20619.65,3774.47 h60
  text "X" at 21758.88,3774.47 h60
  text "20-30 um" at 21886.88,3774.47 h60
  text "BOARD FINISH:" at 20545.2,3626.88 h60
  text "SILKSCREEN:" at 20700.42,3516.75 h60
  text "X" at 21658.2,3516.75 h60
  text "TOP" at 21775.2,3516.75 h60
  text "X" at 22168.2,3516.75 h60
  text "BOTTOM" at 22286.2,3516.75 h60
  text "SILKSCREEN COLOR:" at 20700.42,3361.56 h60
  text "X" at 21657.2,3361.56 h60
  text "WHITE" at 21775.2,3361.56 h60
  text "OTHER" at 22286.2,3361.56 h60
  text "X" at 21788.2,3218.11 h60
  text "GREEN" at 21906.2,3218.11 h60
  text "OTHER" at 22524.2,3218.11 h60
  text "SOLDER RESIST COLOR:" at 20700.42,3211.24 h60
  text "MATTE" at 21906.2,3063.86 h60
  text "SEMI-GLOSS" at 22523.74,3063.22 h60
  text "IMMERSION GOLD (ENIG)" at 21606.2,2891.09 h60
  text "ENEPIG" at 22943.74,2883.87 h60
  text "SURFACE FINISH:" at 20545.2,2882.87 h60
  text "X" at 21428.2,2882.87 h60
  text "IMM. TIN/SILVER OR EQUIV" at 20874.74,2745.55 h60
  text "OTHER" at 22306.2,2741.61 h60
  text "ARRAY/PANEL:" at 20545.2,2586.24 h60
  text "CUT AND TRIM PER M1 BOARD OUTLINE" at 21606.2,2578.02 h60
  text "N.C. ROUTE" at 21606.2,2442.05 h60
  text "X" at 22294.2,2442.05 h60
  text "V. SCORE" at 22472.2,2442.05 h60
  text "CERTIFICATION:" at 20545.2,2312.92 h60
  text "MATERIALS AND WORKMANSHIP FOR ALL PCBS" at 21270.2,2312.92 h60
  text "TO MEET OR EXCEED THE REQUIREMENTS OF:" at 21270.2,2218.86 h60
  text "X" at 20907.71,2090.23 h60
  text "ANSI IPC-A-600F CLASS ->" at 21035.7,2090.23 h60
  text "X" at 22683.71,2090.23 h60
  text "2" at 22793.7,2090.23 h60
  text "1" at 22478.7,2088.73 h60
  text "3" at 23147.7,2088.73 h60
  text "X" at 21719.71,1942.54 h60
  text "RoHS" at 21847.7,1942.54 h60
  text "OTHER" at 22492.1,1942.54 h60
  text "PER ORDER" at 22889.16,1942.54 h60
  text "ALL BOARDS MUST MEET OR EXCEED UL94-V0 REQUIREMENTS." at 20572.74,1788.72 h60
  text "PCB MUST BEAR THE UL94V-0 UL REGISTERED MATERIAL ID NUMBER" at 20572.74,1672.65 h60
  text "ADDITIONAL REQUIREMENTS:" at 20545.2,1503.23 h60
  text "MICROSECTION:" at 20619.97,1396.1 h60
  text "YES" at 21525.7,1396.1 h60
  text "REQUIRED" at 22387.2,1251.77 h60
  text "BARE BOARD ELEC. TEST:" at 20619.97,1248.91 h60
  text "NONE" at 21925.7,1248.91 h60
  text "X" at 22269.2,1248.91 h60
  text "PER ORDER" at 22979.2,1248.91 h60
  text "XX MIL VIAS REQUIRE NON-CONDUCTIVE FILL AND PLANARIZE" at 20788.12,1043.97 h59
  text "XX MIL VIAS REQUIRE CONDUCTIVE FILL AND PLANARIZE" at 20796.12,939.99 h60
  text "OUTER XX MIL TRACES REQUIRE 50 OHM SINGLE-ENDED IMPEDANCE" at 20795.13,776.61 h58
  text "LAYER 2 & 3 (INNER LAYERS) XX MIL WIDE, XX MIL SPACE / TRACES REQUIRE 100 OHM DIFFERENTIAL IMPEDANCE" at 20787.13,540.89 h60
M11 Gerber Information:
  lines w10: -1266.26,-1281.02 5333.74,-1281.02 ; -1266.26,-1077.68 5335.74,-1077.68 ; -1266.26,-874.35 -1266.26,-1484.35 2738.74,-1484.35 5335.74,-1484.35 5335.74,-874.35 -1265.76,-874.35 -1265.76,-1484.35 309.74,-1484.35 ; 1198.74,-1484.35 1198.74,-874.35 ; 2465.74,-1077.68 2465.74,-874.35 ; 3305.74,-1077.68 3305.74,-874.35 ; 3927.74,-1490.85 3927.74,-1288.02
  text "ALL ARTWORK VIEWED FROM TOP SIDE" at -1202.76,-1006.52 h60
  text "BOARD #:" at 1273.74,-1006.52 h60
  text ".PRJ_Number" at 1721,-1006.85 h30
  text "REV:" at 2663.74,-1006.52 h60
  text ".PCB_Rev" at 2955.24,-1006.52 h60
  text "SVN REV:" at 3501.74,-1006.52 h60
  text ".VersionControl_RevNumber" at 4007.74,-1006.52 h60
  text ".TID" at 1648,-1208 h60
  text "LAYER NAME =" at -1202.76,-1209.34 h60
  text "TID #:" at 1273.74,-1209.85 h60
  text ".plot_File_Name" at -523.26,-1397.19 h40
  text "PLOT NAME =" at -1202.76,-1415.19 h60
  text "GENERATED    :" at 1275.74,-1415.19 h60
  text ".Print_Date" at 2145.24,-1415.19 h60
  text ".Print_Time" at 2874.24,-1415.19 h60
  text "TEXAS INSTRUMENTS" at 4138.74,-1415.19 h60
M12 Stackup:
  drawing of 399 lines, arcs and shapes, not listed
  text "Layer" at 15380.5,6405.5 h60
  text "Name" at 15790.41,6405.5 h60
  text "Material" at 16730.15,6405.5 h60
  text "Thickness" at 17589.92,6405.5 h60
  text "Constant" at 18239.76,6405.5 h60
  text "Board Layer Stack" at 18809.62,6405.5 h60
  text "1" at 15380.5,6285.5 h60
  text "Top Overlay" at 15790.41,6285.5 h60
  text "2" at 15380.5,6165.5 h60
  text "Top Solder" at 15790.41,6165.5 h60
  text "Solder Resist" at 16730.15,6165.5 h60
  text "0.40mil" at 17589.92,6165.5 h60
  text "3.5" at 18239.76,6165.5 h60
  text "3" at 15380.5,6045.5 h60
  text "Top Layer" at 15790.41,6045.5 h60
  text "Copper" at 16730.15,6045.5 h60
  text "2.80mil" at 17589.92,6045.5 h60
  text "4" at 15380.5,5925.5 h60
  text "Dielectric 1" at 15790.41,5925.5 h60
  text "FR-4 High Tg" at 16730.15,5925.5 h60
  text "8.00mil" at 17589.92,5925.5 h60
  text "4.2" at 18239.76,5925.5 h60
  text "5" at 15380.5,5805.5 h60
  text "GND Layer" at 15790.41,5805.5 h60
  text "Copper" at 16730.15,5805.5 h60
  text "2.80mil" at 17589.92,5805.5 h60
  text "6" at 15380.5,5685.5 h60
  text "Dielectric2" at 15790.41,5685.5 h60
  text "FR-4 High Tg" at 16730.15,5685.5 h60
  text "8.00mil" at 17589.92,5685.5 h60
  text "4.8" at 18239.76,5685.5 h60
  text "7" at 15380.5,5565.5 h60
  text "Signal Layer 1" at 15790.41,5565.5 h60
  text "Copper" at 16730.15,5565.5 h60
  text "1.40mil" at 17589.92,5565.5 h60
  text "8" at 15380.5,5445.5 h60
  text "Dielectric 3" at 15790.41,5445.5 h60
  text "FR-4 High Tg" at 16730.15,5445.5 h60
  text "16.00mil" at 17589.92,5445.5 h60
  text "4.2" at 18239.76,5445.5 h60
  text "9" at 15380.5,5325.5 h60
  text "Signal Layer 2" at 15790.41,5325.5 h60
  text "Copper" at 16730.15,5325.5 h60
  text "1.40mil" at 17589.92,5325.5 h60
  text "10" at 15380.5,5205.5 h60
  text "Dielectric 4" at 15790.41,5205.5 h60
  text "FR-4 High Tg" at 16730.15,5205.5 h60
  text "8.00mil" at 17589.92,5205.5 h60
  text "4.2" at 18239.76,5205.5 h60
  text "11" at 15380.5,5085.5 h60
  text "Power Layer" at 15790.41,5085.5 h60
  text "Copper" at 16730.15,5085.5 h60
  text "2.80mil" at 17589.92,5085.5 h60
  text "12" at 15380.5,4965.5 h60
  text "Dielectric 5" at 15790.41,4965.5 h60
  text "FR-4 High Tg" at 16730.15,4965.5 h60
  text "8.00mil" at 17589.92,4965.5 h60
  text "4.2" at 18239.76,4965.5 h60
  text "13" at 15380.5,4845.5 h60
  text "Bottom Layer" at 15790.41,4845.5 h60
  text "Copper" at 16730.15,4845.5 h60
  text "2.80mil" at 17589.92,4845.5 h60
  text "14" at 15380.5,4725.5 h60
  text "Bottom Solder" at 15790.41,4725.5 h60
  text "Solder Resist" at 16730.15,4725.5 h60
  text "0.40mil" at 17589.92,4725.5 h60
  text "3.5" at 18239.76,4725.5 h60
  text "15" at 15380.5,4605.5 h60
  text "Bottom Overlay" at 15790.41,4605.5 h60
M13 Component Bodies Top:
  text ".Layer_Name" at -397.26,-1209.34 h60
M14 Component Bodies Bottom:
  text ".Layer_Name" at -397.26,-1209.34 h60
M15 Courtyards Top:
  text ".Layer_Name" at -397.26,-1209.34 h60
M16 Courtyards Bottom:
  text ".Layer_Name" at -397.26,-1209.34 h60
Drill Drawing:
  circle w10: c15513.72,8628.4 r16.58
  circle w10: c15513.72,8628.4 r27.63
  circle w10: c15513.72,8379.76 r27.63
  lines w10: 15486.09,8476.45 15486.09,8490.27 15499.9,8504.08 15486.09,8517.89 15486.09,8531.71 15499.9,8531.71 15513.72,8517.89 15527.53,8531.71 15541.34,8531.71 15541.34,8517.89 15527.53,8504.08 15541.34,8490.27 15541.34,8476.45 15527.53,8476.45 15513.72,8490.27 15499.9,8476.45 15486.09,8476.45 ; 15486.09,8780.35 15541.34,8780.35 15513.72,8725.09 15486.09,8780.35 ; 15486.09,8849.41 15513.72,8863.23 15541.34,8849.41 15527.53,8877.04 15541.34,8904.67 15513.72,8890.85 15486.09,8904.67 15499.9,8877.04 15486.09,8849.41 ; 15486.09,8987.55 15499.9,8987.55 15513.72,8973.73 15527.53,8987.55 15541.34,8987.55 15527.53,9001.36 15541.34,9015.17 15527.53,9015.17 15513.72,9028.99 15499.9,9015.17 15486.09,9015.17 15499.9,9001.36 15486.09,8987.55 ; 15486.09,9098.05 15541.34,9098.05 15541.34,9153.31 15486.09,9153.31 15486.09,9098.05 ; 15486.09,9277.63 15541.34,9277.63 15513.72,9222.37 15486.09,9277.63 ; 15486.09,9360.51 15499.9,9360.51 15513.72,9346.69 15527.53,9360.51 15541.34,9360.51 15527.53,9374.32 15541.34,9388.13 15527.53,9388.13 15513.72,9401.95 15499.9,9388.13 15486.09,9388.13 15499.9,9374.32 15486.09,9360.51 ; 15486.09,9484.83 15499.9,9484.83 15499.9,9471.01 15527.53,9471.01 15527.53,9484.83 15541.34,9484.83 15541.34,9512.45 15527.53,9512.45 15527.53,9526.27 15499.9,9526.27 15499.9,9512.45 15486.09,9512.45 15486.09,9484.83 ; 15486.09,9595.33 15541.34,9595.33 15541.34,9650.59 15486.09,9650.59 15486.09,9595.33 ; 15486.09,9747.28 15513.72,9719.65 15541.34,9747.28 15513.72,9774.91 15486.09,9747.28 ; 15497.14,8769.3 15530.29,8769.3 15513.72,8736.14 15497.14,8769.3 ; 15497.14,8993.07 15505.43,8993.07 15513.72,8984.78 15522.01,8993.07 15530.29,8993.07 15522.01,9001.36 15530.29,9009.65 15522.01,9009.65 15513.72,9017.94 15505.43,9009.65 15497.14,9009.65 15505.43,9001.36 15497.14,8993.07 ; 15497.14,9606.38 15530.29,9606.38 15530.29,9639.54 15497.14,9639.54 15497.14,9606.38
  lines w12: 15436,8314.84 18667.49,8314.84 ; 15436,9806.68 18667.49,9806.68 ; 15773.86,8190.52 15773.86,9931 ; 16105.86,8190.52 16105.86,9931 ; 16742.43,8190.52 16742.43,9931 ; 17001.57,8190.52 17001.57,9931 ; 17376.72,8190.52 17376.72,9931 ; 18101.05,8190.52 18101.05,9931 ; 15436,8190.52 18667.49,8190.52 18667.49,9931 15436,9931 15436,8190.52
  text "Symbol" at 15510.59,9843.97 h72
  text "Quantity" at 15811.16,9843.97 h72
  text "Finished Hole Size" at 16143.16,9843.97 h72
  text "Plated" at 16779.72,9843.97 h72
  text "Hole Type" at 17038.86,9843.97 h72
  text "Drill Layer Pair" at 17414.02,9843.97 h72
  text "Hole Tolerance" at 18138.35,9843.97 h72
  text "40" at 15811.16,9719.65 h60
  text "0.200mm (7.87mil)" at 16143.16,9719.65 h60
  text "PTH" at 16779.72,9719.65 h60
  text "Round" at 17038.86,9719.65 h60
  text "Top Layer - Bottom Layer" at 17414.02,9719.65 h60
  text "1013" at 15811.16,9595.33 h60
  text "0.305mm (12.00mil)" at 16143.16,9595.33 h60
  text "PTH" at 16779.72,9595.33 h60
  text "Round" at 17038.86,9595.33 h60
  text "Top Layer - Bottom Layer" at 17414.02,9595.33 h60
  text "5413" at 15811.16,9471.01 h60
  text "0.406mm (16.00mil)" at 16143.16,9471.01 h60
  text "PTH" at 16779.72,9471.01 h60
  text "Round" at 17038.86,9471.01 h60
  text "Top Layer - Bottom Layer" at 17414.02,9471.01 h60
  text "2" at 15811.16,9346.69 h60
  text "0.840mm (33.07mil)" at 16143.16,9346.69 h60
  text "PTH" at 16779.72,9346.69 h60
  text "Round" at 17038.86,9346.69 h60
  text "Top Layer - Bottom Layer" at 17414.02,9346.69 h60
  text "16" at 15811.16,9222.37 h60
  text "0.900mm (35.43mil)" at 16143.16,9222.37 h60
  text "PTH" at 16779.72,9222.37 h60
  text "Round" at 17038.86,9222.37 h60
  text "Top Layer - Bottom Layer" at 17414.02,9222.37 h60
  text "111" at 15811.16,9098.05 h60
  text "1.016mm (40.00mil)" at 16143.16,9098.05 h60
  text "PTH" at 16779.72,9098.05 h60
  text "Round" at 17038.86,9098.05 h60
  text "Top Layer - Bottom Layer" at 17414.02,9098.05 h60
  text "3" at 15811.16,8973.73 h60
  text "1.020mm (40.16mil)" at 16143.16,8973.73 h60
  text "PTH" at 16779.72,8973.73 h60
  text "Round" at 17038.86,8973.73 h60
  text "Top Layer - Bottom Layer" at 17414.02,8973.73 h60
  text "4" at 15811.16,8849.41 h60
  text "1.270mm (50.00mil)" at 16143.16,8849.41 h60
  text "NPTH" at 16779.72,8849.41 h60
  text "Round" at 17038.86,8849.41 h60
  text "Top Layer - Bottom Layer" at 17414.02,8849.41 h60
  text "3" at 15811.16,8725.09 h60
  text "1.650mm (64.96mil)" at 16143.16,8725.09 h60
  text "PTH" at 16779.72,8725.09 h60
  text "Round" at 17038.86,8725.09 h60
  text "Top Layer - Bottom Layer" at 17414.02,8725.09 h60
  text "9" at 15811.16,8600.77 h60
  text "3.200mm (125.98mil)" at 16143.16,8600.77 h60
  text "NPTH" at 16779.72,8600.77 h60
  text "Round" at 17038.86,8600.77 h60
  text "Top Layer - Bottom Layer" at 17414.02,8600.77 h60
  text "16" at 15811.16,8476.45 h60
  text "3.556mm (140.00mil)" at 16143.16,8476.45 h60
  text "PTH" at 16779.72,8476.45 h60
  text "Round" at 17038.86,8476.45 h60
  text "Top Layer - Bottom Layer" at 17414.02,8476.45 h60
  text "2" at 15811.16,8352.13 h60
  text "4.775mm (188.00mil)" at 16143.16,8352.13 h60
  text "PTH" at 16779.72,8352.13 h60
  text "Round" at 17038.86,8352.13 h60
  text "Top Layer - Bottom Layer" at 17414.02,8352.13 h60
  text "6632 Total" at 15811.16,8227.81 h60
  text "FOR 7.87MIL DRILL +0/-7.87MIL" at 15457,7929 h60
  text "FOR 12MIL DRILL +0/-12MIL" at 15457.18,7829.09 h60
  text "FOR 16MIL DRILL +0/-16MIL" at 15457.18,7724.9 h60
  text "FOR PTH DRILL +/-3MIL" at 15457.18,7620.71 h60
  text "FOR NPTH DRILL +/-2MIL" at 15457.18,7516.52 h60
  text ".Layer_Name" at -397.26,-1209.34 h60
M17 Embedded Cavity:
  text ".Layer_Name" at -397.26,-1209.34 h60
M18 Embedded Assembly:
  text ".Layer_Name" at -397.26,-1209.34 h60
M19 Embedded Keepout:
  text ".Layer_Name" at -397.26,-1209.34 h60

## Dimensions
0,8267.72 to 14763.78,8267.72 on M2 Board Dimensions
0,0 to 0,8267.72 on M2 Board Dimensions
0,0 to 14763.78,0 on M2 Board Dimensions
-974.26,-750.85 to 25.74,-750.85 on M2 Board Dimensions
